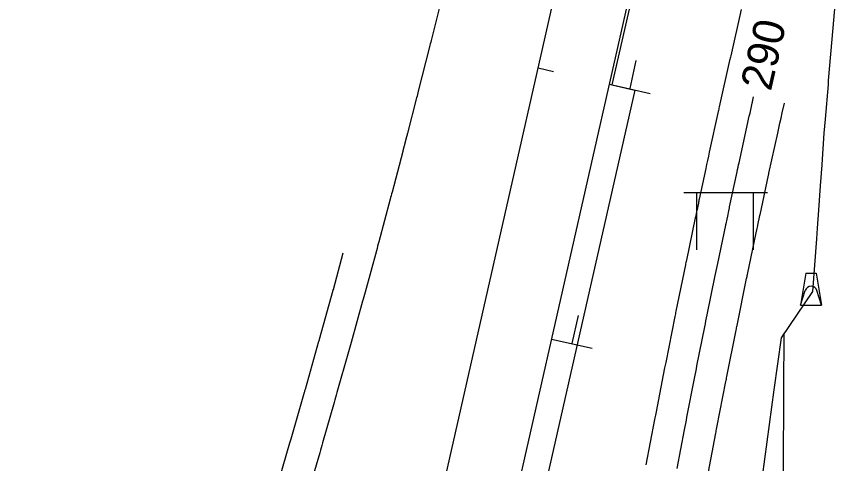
# Model space of a CAD drawing. Extents: x 1710723 to 1713003, y 548603 to 551142.
# Drawn here: x 1712345.3 to 1712502, y 550424.9 to 550510.5 of the extents above; entities that cross this region are included whole.
import ezdxf

# ---------------------------------------------------------------- set-up
doc = ezdxf.new("R2010")
doc.units = 0
for name, color, linetype in [('R_Contour Annot', 7, 'Continuous'), ('R_Contours', 7, 'Continuous'), ('R_Horz Alg', 7, 'Continuous'), ('R_Horz Alg Annot', 7, 'Continuous'), ('R_MOT', 7, 'Continuous'), ('R_No Plot', 7, 'Continuous'), ('R_Striping', 7, 'Continuous'), ('R_Water', 7, 'Continuous')]:
    doc.layers.add(name, color=color, linetype=linetype)

msp = doc.modelspace()

# ---------------------------------------------------------------- linework, layer by layer
at = {"layer": 'R_Contours'}
for points in [[(1712426.7, 550514.31), (1712424.59, 550505.81), (1712424.52, 550505.52), (1712424.44, 550505.22), (1712424.37, 550504.93), (1712424.3, 550504.64), (1712422.15, 550496.17), (1712422.07, 550495.85), (1712421.99, 550495.53), (1712421.91, 550495.21), (1712421.83, 550494.89), (1712420.09, 550488.12), (1712420.04, 550487.95), (1712420, 550487.78), (1712419.95, 550487.6), (1712419.91, 550487.43), (1712419.53, 550485.98), (1712419.5, 550485.84), (1712419.46, 550485.7), (1712419.21, 550484.76), (1712419.2, 550484.72), (1712419.19, 550484.68), (1712419.18, 550484.63), (1712419.17, 550484.59), (1712417.13, 550476.84), (1712417.04, 550476.5), (1712416.95, 550476.16), (1712416.86, 550475.82), (1712416.77, 550475.48), (1712414.59, 550467.35), (1712414.48, 550466.92), (1712414.36, 550466.49), (1712414.25, 550466.07), (1712414.13, 550465.64), (1712411.97, 550457.71), (1712411.85, 550457.27), (1712411.73, 550456.84), (1712411.61, 550456.4), (1712411.49, 550455.97), (1712409.3, 550448.1), (1712409.18, 550447.65), (1712409.05, 550447.19), (1712408.92, 550446.74), (1712408.79, 550446.28), (1712406.59, 550438.49), (1712406.46, 550438.02), (1712406.33, 550437.56), (1712406.19, 550437.09), (1712406.06, 550436.62), (1712403.83, 550428.88), (1712403.69, 550428.41), (1712403.56, 550427.93), (1712403.42, 550427.46), (1712403.28, 550426.98), (1712401.03, 550419.29)], [(1712483.95, 550511.77), (1712481.92, 550502.91), (1712481.87, 550502.68), (1712481.82, 550502.45), (1712481.77, 550502.22), (1712481.71, 550501.99), (1712479.73, 550493.13), (1712479.68, 550492.91), (1712479.63, 550492.69), (1712479.58, 550492.48), (1712479.54, 550492.26), (1712477.83, 550484.47), (1712477.66, 550483.7), (1712477.49, 550482.92), (1712477.32, 550482.15), (1712477.16, 550481.37), (1712475.89, 550475.49), (1712475.85, 550475.3), (1712475.81, 550475.1), (1712475.77, 550474.91), (1712475.73, 550474.71), (1712475.42, 550473.24), (1712475.39, 550473.15), (1712475.37, 550473.05), (1712475.16, 550472.03), (1712475.15, 550471.97), (1712475.13, 550471.91), (1712473.44, 550463.81), (1712473.39, 550463.58), (1712473.35, 550463.36), (1712473.3, 550463.13), (1712473.25, 550462.91), (1712471.45, 550454.08), (1712471.39, 550453.82), (1712471.34, 550453.56), (1712471.29, 550453.3), (1712471.24, 550453.04), (1712469.49, 550444.28), (1712469.44, 550444.01), (1712469.38, 550443.75), (1712469.33, 550443.48), (1712469.28, 550443.21), (1712467.58, 550434.47), (1712467.52, 550434.2), (1712467.47, 550433.93), (1712467.42, 550433.65), (1712467.36, 550433.38), (1712465.71, 550424.66)], [(1712471.68, 550423.99), (1712473.09, 550431.38), (1712473.21, 550431.99), (1712473.32, 550432.6), (1712473.44, 550433.2), (1712473.56, 550433.81), (1712475, 550441.22), (1712475.12, 550441.82), (1712475.24, 550442.42), (1712475.35, 550443.02), (1712475.47, 550443.61), (1712476.96, 550451.05), (1712477.08, 550451.64), (1712477.19, 550452.23), (1712477.31, 550452.82), (1712477.43, 550453.4), (1712478.96, 550460.87), (1712479.08, 550461.45), (1712479.2, 550462.03), (1712479.32, 550462.6), (1712479.44, 550463.18), (1712480.97, 550470.49), (1712480.98, 550470.56), (1712481, 550470.64), (1712481.01, 550470.72), (1712481.03, 550470.8), (1712481.22, 550471.68), (1712481.25, 550471.82), (1712481.28, 550471.95), (1712481.61, 550473.55), (1712481.64, 550473.66), (1712481.66, 550473.77), (1712481.69, 550473.89), (1712481.71, 550474), (1712483.15, 550480.72), (1712483.25, 550481.16), (1712483.34, 550481.6), (1712483.44, 550482.03), (1712483.53, 550482.47), (1712485.22, 550490.17), (1712485.35, 550490.77), (1712485.48, 550491.36), (1712485.62, 550491.96), (1712485.75, 550492.55), (1712486.31, 550495.04)], [(1712477.41, 550422.01), (1712479.07, 550430.74), (1712479.12, 550431), (1712479.17, 550431.27), (1712479.22, 550431.53), (1712479.28, 550431.8), (1712480.99, 550440.61), (1712481.04, 550440.85), (1712481.09, 550441.09), (1712481.13, 550441.33), (1712481.18, 550441.57), (1712482.96, 550450.47), (1712483, 550450.68), (1712483.04, 550450.9), (1712483.09, 550451.12), (1712483.13, 550451.33), (1712484.97, 550460.32), (1712485.01, 550460.51), (1712485.05, 550460.7), (1712485.09, 550460.89), (1712485.13, 550461.08), (1712486.8, 550469.06), (1712486.82, 550469.19), (1712486.85, 550469.31), (1712486.88, 550469.44), (1712486.9, 550469.57), (1712487.09, 550470.45), (1712487.11, 550470.53), (1712487.5, 550472.38), (1712487.51, 550472.44), (1712487.53, 550472.51), (1712489.15, 550480.06), (1712489.17, 550480.16), (1712489.19, 550480.27), (1712489.22, 550480.37), (1712489.24, 550480.47), (1712490.91, 550488.09), (1712491.12, 550489.06), (1712491.34, 550490.03), (1712491.55, 550491.01), (1712491.77, 550491.98), (1712492.2, 550493.88)], [(1712395.02, 550420.07), (1712397.59, 550428.88), (1712397.65, 550429.07), (1712397.7, 550429.26), (1712397.76, 550429.45), (1712397.81, 550429.64), (1712400.39, 550438.59), (1712400.43, 550438.74), (1712400.47, 550438.88), (1712400.52, 550439.03), (1712400.56, 550439.18), (1712403.15, 550448.35), (1712403.18, 550448.43), (1712403.2, 550448.52), (1712403.22, 550448.61), (1712403.25, 550448.69), (1712405.86, 550458.1), (1712405.87, 550458.13), (1712405.88, 550458.17), (1712405.89, 550458.2), (1712405.9, 550458.24), (1712407.8, 550465.22)]]:
    msp.add_lwpolyline(points, dxfattribs=at)
at = {"layer": 'R_Horz Alg'}
msp.add_line((1712246.77, 549627.28), (1712450.81, 550525.82), dxfattribs=at)
at = {"layer": 'R_Horz Alg Annot'}
msp.add_lwpolyline([(1712447.99, 550499.87), (1712445.07, 550500.54)], dxfattribs=at)
at = {"layer": 'R_MOT'}
for p, q in [((1712436.58, 550399.92), (1712464.46, 550522.72)), ((1712462.66, 550496.67), (1712463.86, 550501.99)), ((1712466.51, 550495.67), (1712458.71, 550497.44)), ((1712488.94, 550476.73), (1712472.94, 550476.73)), ((1712475.45, 550465.81), (1712475.45, 550476.73)), ((1712486.31, 550465.81), (1712486.31, 550476.73)), ((1712451.58, 550447.91), (1712452.79, 550453.23)), ((1712455.44, 550446.91), (1712447.64, 550448.68))]:
    msp.add_line(p, q, dxfattribs=at)
for points in [[(1712501.99, 550514.2), (1712501.47, 550508.24), (1712500.6, 550498.18), (1712500.54, 550497.44), (1712499.99, 550490.78), (1712499.77, 550488.12), (1712499.34, 550482.12), (1712499.33, 550482.07), (1712499.05, 550478.03), (1712498.72, 550473.38), (1712498.48, 550469.95), (1712498.34, 550467.93), (1712497.56, 550457.86), (1712491.56, 550448.96), (1712490.17, 550439.03), (1712488.83, 550429.07), (1712487.51, 550419.12)], [(1712492.15, 550449.84), (1712491.56, 550448.96), (1712490.17, 550439.03), (1712488.83, 550429.07), (1712487.51, 550419.12), (1712486.22, 550409.16), (1712484.96, 550399.19), (1712483.75, 550389.21), (1712482.67, 550380.07), (1712482.57, 550379.22), (1712481.44, 550369.23), (1712481, 550365.15), (1712480.5, 550359.18), (1712479.61, 550349.13), (1712478.76, 550339.07), (1712477.98, 550328.99), (1712477.25, 550318.9), (1712476.59, 550308.8), (1712475.95, 550298.69), (1712475.41, 550288.56)], [(1712490.68, 550293.9), (1712490.89, 550310.22), (1712491.1, 550326.54), (1712491.3, 550342.86), (1712491.51, 550359.17), (1712491.64, 550375.22), (1712491.78, 550391.26), (1712491.91, 550407.31), (1712492.04, 550423.35), (1712492.11, 550439.15), (1712492.15, 550449.84)]]:
    msp.add_lwpolyline(points, dxfattribs=at)
at = {"layer": 'R_No Plot'}
for p, q in [((1712464.95, 550522.61), (1712459.21, 550497.33)), ((1712463.59, 550496.33), (1712441.45, 550398.81)), ((1712459.21, 550497.33), (1712463.59, 550496.33))]:
    msp.add_line(p, q, dxfattribs=at)
at = {"layer": 'R_Striping'}
msp.add_line((1712369.36, 550167.14), (1712450.81, 550525.82), dxfattribs=at)
at = {"layer": 'R_Water'}
for p, q in [((1712496.3, 550461.33), (1712495.3, 550455.21)), ((1712496.3, 550461.33), (1712498.3, 550461.33)), ((1712498.3, 550461.33), (1712499.3, 550455.21)), ((1712495.3, 550455.21), (1712496.19, 550458.01)), ((1712499.3, 550455.21), (1712498.41, 550458.01)), ((1712495.3, 550455.21), (1712499.3, 550455.21))]:
    msp.add_line(p, q, dxfattribs=at)
msp.add_arc((1712497.3, 550457.66), 1.17, 17.5299, 162.4701, dxfattribs=at)

# ---------------------------------------------------------------- texts
at = {"layer": 'R_Contour Annot'}
msp.add_text('290', height=6, rotation=77.1735, dxfattribs=at).set_placement((1712489.6, 550495.99))

doc.saveas('drawing.dxf')
